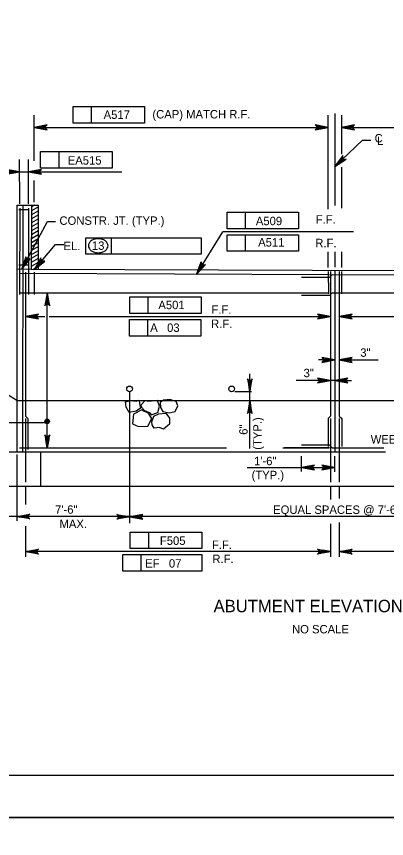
# Model space of a CAD drawing. Extents: x 638340 to 640242, y 295465 to 298435.
# Drawn here: x 638651 to 638783, y 296646 to 296939.5 of the extents above; entities that cross this region are included whole.
import ezdxf

# ---------------------------------------------------------------- set-up
doc = ezdxf.new("R2010")
doc.units = 0
for name, color, linetype in [('2', 7, 'Continuous'), ('3', 7, 'Continuous'), ('4', 7, 'Continuous'), ('Level 10', 7, 'Continuous'), ('Level 3', 7, 'Continuous'), ('Level 4', 7, 'Continuous'), ('Level 5', 7, 'Continuous'), ('PLT-BNDY', 7, 'Continuous')]:
    doc.layers.add(name, color=color, linetype=linetype)

# ---------------------------------------------------------------- blocks, each defined once
blk = doc.blocks.new('ROCK')
at = {"layer": '4'}
for points in [[(2.36725, 1.088), (2.2065, 0.82625), (2.378625, 0.506625), (2.66975, 0.3095), (3.128875, 0.403375), (3.48475, 0.6775), (3.4915, 1.123375), (3.25625, 1.36725), (2.783625, 1.308375)], [(1.10175, -0.02725), (1.4015, -0.159125), (1.78825, -0.148875), (1.980875, -0.266), (2.343375, 0.09475), (2.27875, 0.5505), (1.969375, 0.883), (1.4225, 0.553625), (1.152875, 0.479), (1.0105, 0.082)], [(0.74675, 0.359875), (0.882, 0.16), (1.072875, -0.144), (0.892, -0.457375), (0.448125, -0.758625), (0.1, -0.49325), (-0.095, -0.146375), (0.202875, 0.1025), (0.579125, 0.219875)], [(2.231375, -0.71725), (2.2025, -0.266375), (2.45475, 0.037125), (2.9085, 0.28875), (3.2995, 0.047625), (3.46875, -0.344), (3.231625, -0.855), (2.92, -0.860375), (2.5765, -1.054625), (2.340375, -0.904375)], [(1.2085, -0.192875), (0.778375, -0.737625), (1.008375, -1.391375), (1.48725, -1.396875), (2.09825, -1.106625), (2.133375, -0.486375), (1.723125, -0.203375), (1.37425, -0.239875)]]:
    blk.add_lwpolyline(points, close=True, dxfattribs=at)

msp = doc.modelspace()

# ---------------------------------------------------------------- linework, layer by layer
at = {"layer": '2'}
msp.add_line((639261.46, 296668.46), (638475.46, 296668.46), dxfattribs=at)
at = {"layer": 'Level 10'}
for p, q in [((638764.58, 296904.82), (638764.58, 296871.92)), ((638651.16, 296872.06), (638658.79, 296872.06)), ((638651.16, 296872.06), (638651.16, 296783.96)), ((638653.25, 296872.06), (638653.19, 296783.96)), ((638656.32, 296872.06), (638656.25, 296849.16)), ((638658.83, 296871.47), (638656.36, 296870.05)), ((638657.4, 296872.06), (638656.37, 296871.47)), ((638658.79, 296872.06), (638658.72, 296849.15)), ((638658.82, 296868.63), (638656.34, 296867.2)), ((638658.83, 296870.05), (638656.35, 296868.62)), ((638658.81, 296865.78), (638656.33, 296864.36)), ((638658.81, 296867.21), (638656.34, 296865.78)), ((638658.8, 296864.36), (638656.32, 296862.93)), ((638658.79, 296862.94), (638656.32, 296861.51)), ((638658.71, 296860.06), (638656.3, 296858.67)), ((638658.78, 296861.52), (638656.31, 296860.09)), ((638658.78, 296860.1), (638658.71, 296860.06)), ((638657.62, 296858.01), (638656.29, 296857.25)), ((638658.76, 296857.25), (638656.53, 296855.97)), ((638658.77, 296858.68), (638657.62, 296858.01)), ((638658.75, 296854.41), (638656.27, 296852.98)), ((638658.76, 296855.83), (638656.28, 296854.4)), ((638656.53, 296855.97), (638656.29, 296855.82)), ((638764.58, 296855.41), (638764.58, 296849.89)), ((638658.73, 296851.56), (638656.26, 296850.14)), ((638658.74, 296852.99), (638656.27, 296851.56)), ((638656.25, 296849.16), (638651.05, 296849.18)), ((638872.88, 296848.24), (638656.25, 296849.16)), ((638658.73, 296850.14), (638657.02, 296849.16)), ((638764.58, 296848.55), (638764.58, 296783.96)), ((638651.16, 296802.37), (638584.47, 296842.9)), ((638651.05, 296802.37), (638670.42, 296802.37)), ((638670.42, 296802.37), (638879.84, 296802.37)), ((638581.4, 296783.96), (638729.24, 296783.96)), ((638659.52, 296783.96), (638659.52, 296771.68)), ((638729.24, 296783.96), (638782.6, 296783.96)), ((638961.9, 296771.68), (638581.4, 296771.68))]:
    msp.add_line(p, q, dxfattribs=at)
at = {"layer": 'Level 3'}
for p, q in [((638671.2, 296907.29), (638696.69, 296907.29)), ((638671.2, 296901.4), (638671.2, 296907.29)), ((638677.78, 296901.4), (638677.78, 296907.29)), ((638696.69, 296907.29), (638696.69, 296901.4)), ((638657.27, 296887.93), (638657.27, 296904.25)), ((638762.21, 296870.62), (638762.21, 296904.26)), ((638766.92, 296904.26), (638766.92, 296890.34)), ((638696.69, 296901.4), (638671.2, 296901.4)), ((638657.27, 296899.83), (638762.21, 296899.83)), ((638766.92, 296899.83), (638871.86, 296899.83)), ((638764.58, 296885.92), (638774.42, 296895.29)), ((638774.42, 296895.29), (638777.37, 296895.29)), ((638659.62, 296891.2), (638685.11, 296891.2)), ((638659.62, 296885.31), (638659.62, 296891.2)), ((638666.2, 296885.31), (638666.2, 296891.2)), ((638685.11, 296891.2), (638685.11, 296885.31)), ((638652.14, 296872.57), (638652.07, 296888.39)), ((638655.3, 296872.57), (638655.23, 296888.39)), ((638652.09, 296883.97), (638646.18, 296883.97)), ((638652.07, 296883.97), (638655.23, 296883.97)), ((638655.25, 296883.97), (638688.62, 296883.97)), ((638658.17, 296883.97), (638661.11, 296883.97)), ((638658.18, 296883.97), (638661.12, 296883.97)), ((638685.11, 296885.31), (638659.62, 296885.31)), ((638660.71, 296883.97), (638663.66, 296883.97)), ((638766.92, 296885.59), (638766.92, 296871.06)), ((638657.27, 296873.1), (638657.27, 296880.92)), ((638726.14, 296869.57), (638751.63, 296869.57)), ((638726.14, 296863.68), (638726.14, 296869.57)), ((638732.72, 296863.68), (638732.72, 296869.57)), ((638751.63, 296869.57), (638751.63, 296863.68)), ((638652.92, 296849.17), (638662.02, 296866.27)), ((638662.02, 296866.27), (638664.97, 296866.27)), ((638715.21, 296847.38), (638724.65, 296862.59)), ((638771.21, 296862.59), (638724.65, 296862.59)), ((638751.63, 296863.68), (638726.14, 296863.68)), ((638675.78, 296860.43), (638684.93, 296860.43)), ((638675.78, 296854.53), (638675.78, 296860.43)), ((638684.93, 296854.53), (638684.93, 296860.43)), ((638684.93, 296860.43), (638716.91, 296860.43)), ((638716.91, 296860.43), (638716.91, 296854.53)), ((638726.14, 296861.51), (638751.63, 296861.51)), ((638726.14, 296855.61), (638726.14, 296861.51)), ((638732.72, 296855.61), (638732.72, 296861.51)), ((638751.63, 296861.51), (638751.63, 296855.61)), ((638657.4, 296849.16), (638664.93, 296858.07)), ((638664.93, 296858.07), (638667.88, 296858.07)), ((638716.91, 296854.53), (638675.78, 296854.53)), ((638751.63, 296855.61), (638726.14, 296855.61)), ((638762.21, 296849.88), (638762.21, 296855.41)), ((638766.92, 296855.41), (638766.92, 296849.88)), ((638662, 296813.63), (638662, 296840.75)), ((638691.4, 296839.32), (638716.89, 296839.32)), ((638691.4, 296833.42), (638691.4, 296839.32)), ((638697.98, 296833.42), (638697.98, 296839.32)), ((638716.89, 296839.32), (638716.89, 296833.42)), ((638716.89, 296833.42), (638691.4, 296833.42)), ((638654.16, 296832.34), (638661.1, 296832.34)), ((638662.61, 296832.34), (638763.04, 296832.34)), ((638691.31, 296825.36), (638691.31, 296831.25)), ((638691.31, 296831.25), (638716.8, 296831.25)), ((638697.89, 296825.36), (638697.89, 296831.25)), ((638716.8, 296831.25), (638716.8, 296825.36)), ((638766.11, 296832.34), (638865.48, 296832.34)), ((638716.8, 296825.36), (638691.31, 296825.36)), ((638764.58, 296816.82), (638758.68, 296816.82)), ((638766.11, 296816.82), (638779.96, 296816.82)), ((638662, 296785.49), (638662, 296813.63)), ((638734.2, 296785.16), (638734.2, 296811.91)), ((638757.15, 296809.49), (638750.8, 296809.49)), ((638763.04, 296809.49), (638757.15, 296809.49)), ((638764.58, 296809.49), (638763.04, 296809.49)), ((638764.58, 296809.49), (638770.47, 296809.49)), ((638734.8, 296805.45), (638728.85, 296805.45)), ((638600.3, 296794.53), (638662, 296794.53)), ((638651.16, 296783.1), (638651.16, 296759.33)), ((638752.69, 296777), (638752.69, 296782.5)), ((638764.58, 296776.86), (638764.58, 296782.5)), ((638733.3, 296778.42), (638764.58, 296778.42)), ((638654.16, 296771.68), (638654.16, 296765.2)), ((638763.04, 296771.68), (638763.04, 296766.96)), ((638766.11, 296771.68), (638766.11, 296767.31)), ((638883.14, 296760.94), (638597.64, 296760.94)), ((638654.16, 296757.43), (638654.16, 296746.58)), ((638763.04, 296758.37), (638763.04, 296746.49)), ((638763.04, 296757.94), (638763.04, 296756.92)), ((638766.11, 296758.8), (638766.11, 296746.49)), ((638766.11, 296758.64), (638766.11, 296756.92)), ((638691.57, 296749.49), (638691.57, 296755.38)), ((638691.57, 296755.38), (638717.06, 296755.38)), ((638698.15, 296749.49), (638698.15, 296755.38)), ((638717.06, 296755.38), (638717.06, 296749.49)), ((638763.04, 296748.4), (638654.16, 296748.4)), ((638717.06, 296749.49), (638691.57, 296749.49)), ((638879.89, 296748.4), (638766.11, 296748.4)), ((638688.92, 296747.32), (638717.14, 296747.32)), ((638688.92, 296741.42), (638688.92, 296747.32)), ((638695.5, 296741.42), (638695.5, 296747.32)), ((638717.14, 296747.32), (638717.14, 296741.42)), ((638717.14, 296741.42), (638688.92, 296741.42))]:
    msp.add_line(p, q, dxfattribs=at)
for points in [[(638657.27, 296899.83), (638661.92, 296898.96), (638661.56, 296899.21), (638661.38, 296899.52), (638661.32, 296899.83), (638661.38, 296900.14), (638661.56, 296900.45), (638661.92, 296900.7), (638657.27, 296899.83), (638661.56, 296900.45), (638661.38, 296900.14), (638657.27, 296899.83), (638661.32, 296899.83), (638661.38, 296899.52), (638657.27, 296899.83), (638661.56, 296899.21)], [(638762.21, 296899.83), (638757.56, 296900.7), (638757.91, 296900.45), (638758.1, 296900.14), (638758.15, 296899.83), (638758.1, 296899.52), (638757.91, 296899.21), (638757.56, 296898.96), (638762.21, 296899.83), (638757.91, 296899.21), (638758.1, 296899.52), (638762.21, 296899.83), (638758.15, 296899.83), (638758.1, 296900.14), (638762.21, 296899.83), (638757.91, 296900.45)], [(638766.92, 296899.83), (638771.57, 296898.96), (638771.21, 296899.21), (638771.03, 296899.52), (638770.97, 296899.83), (638771.03, 296900.14), (638771.21, 296900.45), (638771.57, 296900.7), (638766.92, 296899.83), (638771.21, 296900.45), (638771.03, 296900.14), (638766.92, 296899.83), (638770.97, 296899.83), (638771.03, 296899.52), (638766.92, 296899.83), (638771.21, 296899.21)], [(638764.58, 296885.92), (638768.55, 296888.49), (638768.12, 296888.43), (638767.77, 296888.53), (638767.52, 296888.71), (638767.34, 296888.98), (638767.26, 296889.33), (638767.35, 296889.76), (638764.58, 296885.92), (638767.26, 296889.33), (638767.34, 296888.98), (638764.58, 296885.92), (638767.52, 296888.71), (638767.77, 296888.53), (638764.58, 296885.92), (638768.12, 296888.43)], [(638652.09, 296883.97), (638647.44, 296884.84), (638647.8, 296884.6), (638647.98, 296884.29), (638648.03, 296883.97), (638647.98, 296883.66), (638647.8, 296883.35), (638647.44, 296883.1), (638652.09, 296883.97), (638647.8, 296883.35), (638647.98, 296883.66), (638652.09, 296883.97), (638648.03, 296883.97), (638647.98, 296884.29), (638652.09, 296883.97), (638647.8, 296884.6)], [(638655.25, 296883.97), (638659.9, 296883.1), (638659.54, 296883.35), (638659.36, 296883.66), (638659.31, 296883.97), (638659.36, 296884.29), (638659.54, 296884.6), (638659.9, 296884.84), (638655.25, 296883.97), (638659.54, 296884.6), (638659.36, 296884.29), (638655.25, 296883.97), (638659.31, 296883.97), (638659.36, 296883.66), (638655.25, 296883.97), (638659.54, 296883.35)], [(638652.92, 296849.17), (638655.87, 296852.87), (638655.49, 296852.67), (638655.12, 296852.65), (638654.82, 296852.75), (638654.57, 296852.95), (638654.39, 296853.26), (638654.33, 296853.69), (638652.92, 296849.17), (638654.39, 296853.26), (638654.57, 296852.95), (638652.92, 296849.17), (638654.82, 296852.75), (638655.12, 296852.65), (638652.92, 296849.17), (638655.49, 296852.67)], [(638657.4, 296849.16), (638661.07, 296852.14), (638660.64, 296852.03), (638660.29, 296852.09), (638660.01, 296852.25), (638659.81, 296852.49), (638659.69, 296852.84), (638659.73, 296853.27), (638657.4, 296849.16), (638659.69, 296852.84), (638659.81, 296852.49), (638657.4, 296849.16), (638660.01, 296852.25), (638660.29, 296852.09), (638657.4, 296849.16), (638660.64, 296852.03)], [(638715.21, 296847.38), (638716.92, 296851.79), (638716.95, 296851.35), (638717.11, 296851.03), (638717.35, 296850.82), (638717.64, 296850.7), (638718.01, 296850.69), (638718.4, 296850.87), (638715.21, 296847.38), (638718.01, 296850.69), (638717.64, 296850.7), (638715.21, 296847.38), (638717.35, 296850.82), (638717.11, 296851.03), (638715.21, 296847.38), (638716.95, 296851.35)], [(638662, 296840.75), (638661.13, 296836.1), (638661.38, 296836.46), (638661.69, 296836.64), (638662, 296836.69), (638662.31, 296836.64), (638662.62, 296836.46), (638662.87, 296836.1), (638662, 296840.75), (638662.62, 296836.46), (638662.31, 296836.64), (638662, 296840.75), (638662, 296836.69), (638661.69, 296836.64), (638662, 296840.75), (638661.38, 296836.46)], [(638654.16, 296832.33), (638658.81, 296831.46), (638658.45, 296831.71), (638658.27, 296832.02), (638658.22, 296832.33), (638658.27, 296832.65), (638658.45, 296832.96), (638658.81, 296833.21), (638654.16, 296832.33), (638658.45, 296832.96), (638658.27, 296832.65), (638654.16, 296832.33), (638658.22, 296832.33), (638658.27, 296832.02), (638654.16, 296832.33), (638658.45, 296831.71)], [(638763.04, 296832.33), (638758.39, 296833.21), (638758.75, 296832.96), (638758.94, 296832.65), (638758.99, 296832.33), (638758.94, 296832.02), (638758.75, 296831.71), (638758.39, 296831.46), (638763.04, 296832.33), (638758.75, 296831.71), (638758.94, 296832.02), (638763.04, 296832.33), (638758.99, 296832.33), (638758.94, 296832.65), (638763.04, 296832.33), (638758.75, 296832.96)], [(638766.11, 296832.33), (638770.77, 296831.46), (638770.41, 296831.71), (638770.22, 296832.02), (638770.17, 296832.33), (638770.22, 296832.65), (638770.41, 296832.96), (638770.77, 296833.21), (638766.11, 296832.33), (638770.41, 296832.96), (638770.22, 296832.65), (638766.11, 296832.33), (638770.17, 296832.33), (638770.22, 296832.02), (638766.11, 296832.33), (638770.41, 296831.71)], [(638764.58, 296816.82), (638759.93, 296817.69), (638760.29, 296817.44), (638760.47, 296817.13), (638760.52, 296816.82), (638760.47, 296816.51), (638760.29, 296816.19), (638759.93, 296815.94), (638764.58, 296816.82), (638760.29, 296816.19), (638760.47, 296816.51), (638764.58, 296816.82), (638760.52, 296816.82), (638760.47, 296817.13), (638764.58, 296816.82), (638760.29, 296817.44)], [(638766.11, 296816.82), (638770.77, 296815.95), (638770.41, 296816.19), (638770.22, 296816.51), (638770.17, 296816.82), (638770.22, 296817.13), (638770.41, 296817.44), (638770.77, 296817.69), (638766.11, 296816.82), (638770.41, 296817.44), (638770.22, 296817.13), (638766.11, 296816.82), (638770.17, 296816.82), (638770.22, 296816.51), (638766.11, 296816.82), (638770.41, 296816.19)], [(638734.22, 296805.45), (638735.09, 296810.1), (638734.85, 296809.74), (638734.53, 296809.55), (638734.22, 296809.5), (638733.91, 296809.55), (638733.6, 296809.74), (638733.35, 296810.1), (638734.22, 296805.45), (638733.6, 296809.74), (638733.91, 296809.55), (638734.22, 296805.45), (638734.22, 296809.5), (638734.53, 296809.55), (638734.22, 296805.45), (638734.85, 296809.74)], [(638763.04, 296809.49), (638758.39, 296810.36), (638758.75, 296810.11), (638758.94, 296809.8), (638758.99, 296809.49), (638758.94, 296809.17), (638758.75, 296808.86), (638758.39, 296808.61), (638763.04, 296809.49), (638758.75, 296808.86), (638758.94, 296809.17), (638763.04, 296809.49), (638758.99, 296809.49), (638758.94, 296809.8), (638763.04, 296809.49), (638758.75, 296810.11)], [(638764.58, 296809.49), (638769.23, 296808.61), (638768.87, 296808.86), (638768.69, 296809.17), (638768.63, 296809.49), (638768.69, 296809.8), (638768.87, 296810.11), (638769.23, 296810.36), (638764.58, 296809.49), (638768.87, 296810.11), (638768.69, 296809.8), (638764.58, 296809.49), (638768.63, 296809.49), (638768.69, 296809.17), (638764.58, 296809.49), (638768.87, 296808.86)], [(638734.2, 296802.37), (638733.33, 296797.72), (638733.58, 296798.08), (638733.89, 296798.27), (638734.2, 296798.32), (638734.51, 296798.27), (638734.83, 296798.08), (638735.07, 296797.72), (638734.2, 296802.37), (638734.83, 296798.08), (638734.51, 296798.27), (638734.2, 296802.37), (638734.2, 296798.32), (638733.89, 296798.27), (638734.2, 296802.37), (638733.58, 296798.08)], [(638662, 296785.49), (638662.87, 296790.14), (638662.62, 296789.78), (638662.31, 296789.6), (638662, 296789.54), (638661.69, 296789.6), (638661.38, 296789.78), (638661.13, 296790.14), (638662, 296785.49), (638661.38, 296789.78), (638661.69, 296789.6), (638662, 296785.49), (638662, 296789.54), (638662.31, 296789.6), (638662, 296785.49), (638662.62, 296789.78)], [(638752.63, 296778.42), (638757.28, 296777.55), (638756.92, 296777.8), (638756.73, 296778.11), (638756.68, 296778.42), (638756.73, 296778.73), (638756.92, 296779.04), (638757.28, 296779.29), (638752.63, 296778.42), (638756.92, 296779.04), (638756.73, 296778.73), (638752.63, 296778.42), (638756.68, 296778.42), (638756.73, 296778.11), (638752.63, 296778.42), (638756.92, 296777.8)], [(638764.58, 296778.42), (638759.93, 296779.29), (638760.29, 296779.04), (638760.47, 296778.73), (638760.52, 296778.42), (638760.47, 296778.11), (638760.29, 296777.8), (638759.93, 296777.55), (638764.58, 296778.42), (638760.29, 296777.8), (638760.47, 296778.11), (638764.58, 296778.42), (638760.52, 296778.42), (638760.47, 296778.73), (638764.58, 296778.42), (638760.29, 296779.04)], [(638654.16, 296748.4), (638658.81, 296749.27), (638658.45, 296749.02), (638658.27, 296748.71), (638658.22, 296748.4), (638658.27, 296748.09), (638658.45, 296747.77), (638658.81, 296747.53), (638654.16, 296748.4), (638658.45, 296747.77), (638658.27, 296748.09), (638654.16, 296748.4), (638658.22, 296748.4), (638658.27, 296748.71), (638654.16, 296748.4), (638658.45, 296749.02)], [(638763.04, 296748.4), (638758.39, 296747.53), (638758.75, 296747.77), (638758.94, 296748.09), (638758.99, 296748.4), (638758.94, 296748.71), (638758.75, 296749.02), (638758.39, 296749.27), (638763.04, 296748.4), (638758.75, 296749.02), (638758.94, 296748.71), (638763.04, 296748.4), (638758.99, 296748.4), (638758.94, 296748.09), (638763.04, 296748.4), (638758.75, 296747.77)], [(638766.11, 296748.4), (638770.77, 296749.27), (638770.41, 296749.02), (638770.22, 296748.71), (638770.17, 296748.4), (638770.22, 296748.09), (638770.41, 296747.77), (638770.77, 296747.53), (638766.11, 296748.4), (638770.41, 296747.77), (638770.22, 296748.09), (638766.11, 296748.4), (638770.17, 296748.4), (638770.22, 296748.71), (638766.11, 296748.4), (638770.41, 296749.02)]]:
    msp.add_lwpolyline(points, dxfattribs=at)
for points in [[(638767.06, 296887.58), (638766.39, 296888.3), (638764.58, 296885.92)], [(638649.12, 296884.46), (638649.12, 296883.48), (638652.07, 296883.97)], [(638658.18, 296884.46), (638658.18, 296883.48), (638655.23, 296883.97)], [(638654.74, 296851.55), (638653.87, 296852.01), (638652.92, 296849.17)], [(638659.68, 296851.09), (638658.92, 296851.72), (638657.4, 296849.16)], [(638661.51, 296837.8), (638662.49, 296837.8), (638662, 296840.75)], [(638760.1, 296832.83), (638760.1, 296831.84), (638763.04, 296832.33)], [(638769.06, 296832.83), (638769.06, 296831.84), (638766.11, 296832.33)], [(638761.63, 296817.31), (638761.63, 296816.33), (638764.58, 296816.82)], [(638769.06, 296817.31), (638769.06, 296816.33), (638766.11, 296816.82)], [(638760.1, 296809.98), (638760.1, 296808.99), (638763.04, 296809.49)], [(638767.53, 296809.98), (638767.53, 296808.99), (638764.58, 296809.49)], [(638733.71, 296799.43), (638734.69, 296799.43), (638734.2, 296802.37)], [(638661.51, 296788.44), (638662.49, 296788.44), (638662, 296785.49)], [(638760.1, 296748.89), (638760.1, 296747.91), (638763.04, 296748.4)], [(638769.06, 296748.89), (638769.06, 296747.91), (638766.11, 296748.4)]]:
    msp.add_lwpolyline(points, close=True, dxfattribs=at)
for centre, radius in [((638691.32, 296806.47), 1.02), ((638727.74, 296806.47), 1.02), ((638661.94, 296794.9), 0.832), ((638661.94, 296794.9), 0.416)]:
    msp.add_circle(centre, radius, dxfattribs=at)
for centre, radius, start, end in [((638679.81, 296856.39), 3.65, 106.5358, 125.6316), ((638680.15, 296855.23), 4.86, 90, 106.5358), ((638680.15, 296855.23), 4.86, 73.4642, 90), ((638680.49, 296856.39), 3.65, 54.3684, 73.4642), ((638678.48, 296857.59), 1.82, 149.9767, 180), ((638678.48, 296857.59), 1.82, 180, 210.0233), ((638679.28, 296857.12), 2.75, 125.6316, 149.9767), ((638679.28, 296858.05), 2.75, 210.0233, 234.3684), ((638681.02, 296857.12), 2.75, 30.0233, 54.3684), ((638681.02, 296858.05), 2.75, 305.6316, 329.9767), ((638681.82, 296857.59), 1.82, 0, 30.0233), ((638681.82, 296857.59), 1.82, 329.9767, 0), ((638679.81, 296858.79), 3.65, 234.3684, 253.4642), ((638680.15, 296859.94), 4.86, 253.4642, 270), ((638680.15, 296859.94), 4.86, 270, 286.5358), ((638680.49, 296858.79), 3.65, 286.5358, 305.6316)]:
    msp.add_arc(centre, radius, start, end, dxfattribs=at)
at = {"layer": 'Level 4'}
for points in [[(638651.16, 296760.94), (638655.81, 296761.81), (638655.46, 296761.56), (638655.27, 296761.25), (638655.22, 296760.94), (638655.27, 296760.63), (638655.46, 296760.32), (638655.81, 296760.07), (638651.16, 296760.94), (638655.46, 296760.32), (638655.27, 296760.63), (638651.16, 296760.94), (638655.22, 296760.94), (638655.27, 296761.25), (638651.16, 296760.94), (638655.46, 296761.56)], [(638691.43, 296760.8), (638686.78, 296759.93), (638687.14, 296760.18), (638687.32, 296760.49), (638687.38, 296760.8), (638687.32, 296761.12), (638687.14, 296761.43), (638686.78, 296761.68), (638691.43, 296760.8), (638687.14, 296761.43), (638687.32, 296761.12), (638691.43, 296760.8), (638687.38, 296760.8), (638687.32, 296760.49), (638691.43, 296760.8), (638687.14, 296760.18)], [(638691.43, 296760.8), (638696.08, 296759.93), (638695.73, 296760.18), (638695.54, 296760.49), (638695.49, 296760.8), (638695.54, 296761.12), (638695.73, 296761.43), (638696.08, 296761.68), (638691.43, 296760.8), (638695.73, 296761.43), (638695.54, 296761.12), (638691.43, 296760.8), (638695.49, 296760.8), (638695.54, 296760.49), (638691.43, 296760.8), (638695.73, 296760.18)]]:
    msp.add_lwpolyline(points, dxfattribs=at)
at = {"layer": 'Level 5'}
for p, q in [((638651.88, 296870.53), (638655.55, 296870.53)), ((638652.14, 296871.04), (638652.07, 296840.24)), ((638655.3, 296871.04), (638655.23, 296840.24)), ((638655.49, 296850.7), (638651.82, 296850.7)), ((638654.16, 296848.15), (638654.16, 296796.8)), ((638657.27, 296848.15), (638657.29, 296840.24)), ((638762.21, 296848.38), (638762.23, 296840.47)), ((638763.04, 296848.38), (638763.04, 296796.8)), ((638766.11, 296848.38), (638766.11, 296796.8)), ((638766.92, 296848.38), (638766.93, 296840.47)), ((638762.61, 296847.17), (638652.07, 296847.64)), ((638762.61, 296846.24), (638752.69, 296846.28)), ((638763.54, 296847.17), (638762.61, 296846.24)), ((638882.01, 296846.67), (638763.54, 296847.17)), ((638652.07, 296840.75), (638762.51, 296840.75)), ((638762.63, 296839.82), (638752.7, 296839.82)), ((638763.56, 296840.75), (638762.63, 296839.82)), ((638763.56, 296840.75), (638882.01, 296840.75)), ((638691.32, 296805.45), (638691.32, 296758.56)), ((638654.16, 296796.8), (638655.09, 296795.87)), ((638654.16, 296795.87), (638654.16, 296773.21)), ((638655.09, 296795.87), (638655.09, 296784.85)), ((638763.04, 296796.8), (638762.11, 296795.87)), ((638762.11, 296795.87), (638762.11, 296785.95)), ((638763.04, 296795.87), (638763.04, 296773.21)), ((638766.11, 296796.8), (638767.05, 296795.87)), ((638766.11, 296795.87), (638766.11, 296773.21)), ((638767.05, 296795.87), (638767.05, 296785.95)), ((638762.63, 296786.42), (638752.7, 296786.42)), ((638763.56, 296785.49), (638762.63, 296786.42)), ((638652.07, 296785.49), (638725.88, 296785.49)), ((638746, 296785.49), (638762.51, 296785.49)), ((638762.63, 296785.49), (638746.56, 296785.49)), ((638763.56, 296785.49), (638782.06, 296785.49))]:
    msp.add_line(p, q, dxfattribs=at)
at = {"layer": 'PLT-BNDY'}
for points in [[(638435.46, 297247.46), (639276.46, 297247.46), (639276.46, 296653.46), (638435.46, 296653.46)], [(638435.46, 296653.46), (639276.46, 296653.46), (639276.46, 296059.46), (638435.46, 296059.46)]]:
    msp.add_lwpolyline(points, close=True, dxfattribs=at)

# ---------------------------------------------------------------- block references
at = {"layer": 'Level 3', "xscale": 4.9118761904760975, "yscale": 4.911876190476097, "rotation": -23.78336161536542}
msp.add_blockref('ROCK', (638690.64, 296802.32), dxfattribs=at)

# ---------------------------------------------------------------- texts
at = {"layer": '3'}
for s, height, p in [('ABUTMENT ELEVATION', 4.4294, (638721.3, 296726.76)), ('NO SCALE', 3, (638749.26, 296719.2))]:
    msp.add_text(s, height=height, dxfattribs=at).set_placement(p)
at = {"layer": 'Level 3'}
for s, height, p in [('A517', 3, (638682.08, 296902.88)), ('(CAP) MATCH R.F.', 3.0001, (638699.47, 296903.04)), ('C', 3, (638778.72, 296894.47)), ('L', 3, (638779.57, 296893.58)), ('EA515', 3, (638669.29, 296886.56)), ('F.F.', 3, (638757.74, 296865.49)), ('CONSTR. JT. (TYP.)', 3.0001, (638666.32, 296865.06)), ('A509', 3, (638736.37, 296864.93)), ('A511', 3, (638737.2, 296857.31)), ('R.F.', 3, (638757.57, 296857.07)), ('EL.', 3, (638667.77, 296856.02)), ('13', 3, (638677.9, 296856.13)), ('A501', 3, (638701.6, 296834.95)), ('F.F.', 3, (638720.55, 296833.29)), ('R.F.', 3, (638720.39, 296828.23)), ('A   03', 3, (638698.69, 296826.84)), ('3"', 3, (638773.61, 296817.95)), ('3"', 3, (638753.39, 296810.66)), ('WEEPHOLE', 3, (638777.34, 296786.98)), ('1\'-6"', 3, (638735.72, 296779.24)), ('(TYP.)', 3, (638734.84, 296774.24)), ('7\'-6"', 3, (638664.77, 296761.91)), ('EQUAL SPACES @ 7\'-6" MAX.', 3.0001, (638742.53, 296761.86)), ('MAX.', 3, (638666.34, 296756.8)), ('F505', 3, (638702.15, 296750.8)), ('F.F.', 3, (638720.7, 296749.35)), ('EF   07', 3, (638696.89, 296742.69)), ('R.F.', 3, (638720.85, 296744.3))]:
    msp.add_text(s, height=height, dxfattribs=at).set_placement(p)
for s, p in [('(TYP.)', (638738.43, 296784.75)), ('6"', (638733.44, 296790.1))]:
    msp.add_text(s, height=3, rotation=90, dxfattribs=at).set_placement(p)

doc.saveas('drawing.dxf')
